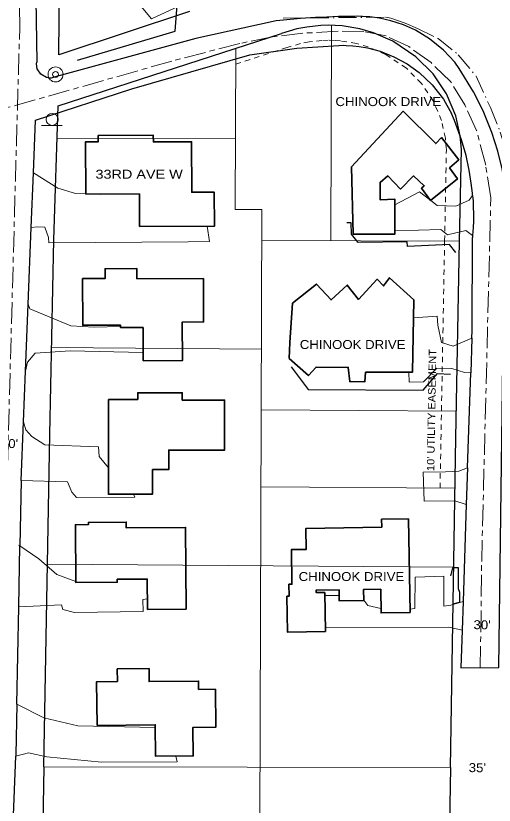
# Model space of a CAD drawing. Extents: x -861682 to -858969, y -1797841 to -1795153.
# Drawn here: x -860995 to -860675, y -1797216 to -1796688 of the extents above; entities that cross this region are included whole.
import ezdxf

# ---------------------------------------------------------------- set-up
doc = ezdxf.new("R2010")
doc.units = 0
doc.header["$LTSCALE"] = 2.4
for name, pattern in [('DOT_DASHED', [7.7, 5, -1.2, 0.3, -1.2]), ('LONG_DASH_SHORT_DASH', [9.9, 6, -1.2, 1.5, -1.2]), ('SHORT_DASHED', [2.7, 1.5, -1.2])]:
    doc.linetypes.add(name, pattern=pattern)
for name, color, linetype, lineweight in [('10', 7, 'Continuous', 25), ('11', 7, 'Continuous', 13), ('12', 7, 'Continuous', 35), ('14', 7, 'Continuous', 25), ('21', 7, 'Continuous', 13), ('30', 7, 'Continuous', 13), ('31', 7, 'Continuous', 13), ('32', 7, 'LONG_DASH_SHORT_DASH', 13), ('42', 7, 'Continuous', 25), ('46', 7, 'Continuous', 13), ('47', 7, 'SHORT_DASHED', 13), ('63', 7, 'DOT_DASHED', 13)]:
    doc.layers.add(name, color=color, linetype=linetype, lineweight=lineweight)
doc.layers.add('43', color=7, linetype='Continuous')

msp = doc.modelspace()

# ---------------------------------------------------------------- linework, layer by layer
at = {"layer": '10'}
for p, q in [((-860689.539, -1796835.154), (-860689.633, -1796836.516)), ((-860690.025, -1796903.667), (-860690.806, -1796926.828)), ((-860692.948, -1796990.368), (-860690.806, -1796926.828)), ((-860991.269, -1796998.783), (-860989.701, -1796959.723)), ((-860692.948, -1796990.368), (-860693.774, -1797014.844)), ((-860991.269, -1796998.783), (-860992.108, -1797042.6)), ((-860693.774, -1797014.844), (-860695.962, -1797079.745)), ((-860992.889, -1797083.299), (-860992.108, -1797042.6)), ((-860994.136, -1797148.307), (-860992.889, -1797083.299)), ((-860695.962, -1797079.745), (-860696.61, -1797098.951)), ((-860998.692, -1797277.689), (-860994.825, -1797183.063))]:
    msp.add_line(p, q, dxfattribs=at)
for points in [[(-860916.639, -1796531.103), (-860972.545, -1796545.521), (-860983.387, -1796550.997), (-860980.82, -1796719.365)], [(-860768.16, -1796688.758), (-860772.568, -1796688.802), (-860779.179, -1796688.94), (-860786.888, -1796689.21), (-860794.592, -1796689.598), (-860804.487, -1796690.269), (-860815.84, -1796691.279), (-860820.813, -1796691.804)], [(-860701.439, -1796719.429), (-860708.938, -1796711.364), (-860718.335, -1796703.724), (-860727.76, -1796698.028), (-860735.79, -1796694.4), (-860744.159, -1796691.642), (-860751.686, -1796689.967), (-860758.238, -1796689.091), (-860763.161, -1796688.778), (-860764.263, -1796688.748), (-860766.467, -1796688.731), (-860768.16, -1796688.758)], [(-860820.813, -1796691.804), (-860874.61, -1796703.591), (-860967.555, -1796728.994)], [(-860983.021, -1796793.297), (-860981.609, -1796758.099), (-860917.22, -1796737.296), (-860838.434, -1796714.546), (-860807.043, -1796709.934), (-860778.947, -1796708.168)], [(-860778.947, -1796708.168), (-860776.151, -1796708.12), (-860773.947, -1796708.151), (-860769.635, -1796708.386), (-860765.254, -1796708.864), (-860759.824, -1796709.798), (-860751.308, -1796712.058), (-860742.087, -1796715.695), (-860733.384, -1796720.438), (-860725.33, -1796726.215), (-860716.544, -1796734.55), (-860709.109, -1796744.11), (-860703.664, -1796753.68)], [(-860967.555, -1796728.994), (-860971.294, -1796729.991), (-860972.395, -1796729.978), (-860974.368, -1796729.618), (-860978.135, -1796727.412), (-860980.461, -1796723.717), (-860980.927, -1796720.462), (-860980.82, -1796719.365)], [(-860667.811, -1796801.476), (-860669.755, -1796790.631), (-860672.633, -1796778.858), (-860676.642, -1796766.259), (-860682.438, -1796751.966), (-860688.867, -1796739.167), (-860698.547, -1796723.507), (-860701.439, -1796719.429)], [(-860689.551, -1796808.418), (-860689.672, -1796806.801), (-860690.405, -1796800.231), (-860691.788, -1796791.525), (-860693.895, -1796781.835), (-860696.91, -1796771.237), (-860701.676, -1796758.268), (-860703.664, -1796753.68)], [(-860989.701, -1796959.723), (-860988.341, -1796925.855), (-860986.543, -1796881.068), (-860984.485, -1796829.787), (-860983.021, -1796793.297)], [(-860696.61, -1797098.951), (-860697.453, -1797123.953), (-860671.948, -1797123.851), (-860667.811, -1796801.476)], [(-860689.551, -1796808.418), (-860689.262, -1796812.296), (-860689.066, -1796816.699), (-860688.996, -1796820.005), (-860688.986, -1796822.209), (-860689.025, -1796825.514), (-860689.18, -1796829.919), (-860689.539, -1796835.154)], [(-860690.025, -1796903.667), (-860689.856, -1796898.626), (-860689.633, -1796836.516)], [(-860994.136, -1797148.307), (-860994.784, -1797182.056), (-860994.825, -1797183.063)]]:
    msp.add_lwpolyline(points, dxfattribs=at)
at = {"layer": '11'}
for p, q in [((-860992.984, -1797042.007), (-860992.108, -1797042.6)), ((-860778.687, -1797075.629), (-860788.31, -1797075.667))]:
    msp.add_line(p, q, dxfattribs=at)
for points in [[(-860917.95, -1796673.813), (-860904.185, -1796690.487), (-860886.27, -1796682.149), (-860889.617, -1796554.163), (-860889.673, -1796540.23), (-860887.335, -1796534.316), (-860882.579, -1796542.563), (-860882.222, -1796572.554), (-860882.597, -1796596.88), (-860881.856, -1796604.907), (-860856.836, -1796601.737), (-860864.668, -1796569.117)], [(-860948.073, -1796807.381), (-860954.962, -1796807.114), (-860966.784, -1796803.618), (-860983.021, -1796793.297)], [(-860935.223, -1796807.505), (-860938.428, -1796807.756), (-860943.977, -1796807.54)], [(-860741.477, -1796814.681), (-860724.945, -1796805.957), (-860717.552, -1796811.792), (-860713.336, -1796815.121), (-860700.818, -1796815.543), (-860691.86, -1796811.493), (-860689.551, -1796808.418)], [(-860867.012, -1796828.959), (-860865.327, -1796839.108), (-860879.732, -1796839.402), (-860972.778, -1796840.011), (-860973.028, -1796836.47), (-860975.417, -1796829.63), (-860980.378, -1796829.414), (-860984.485, -1796829.787)], [(-860741.581, -1796831.766), (-860725.786, -1796831.702), (-860710.674, -1796831.17), (-860706.409, -1796834.695), (-860694.14, -1796831.811), (-860689.539, -1796835.154)], [(-860924.846, -1796896.031), (-860942.559, -1796896.332), (-860958.149, -1796895.45), (-860985.353, -1796884.223), (-860986.543, -1796881.068)], [(-860729.091, -1796890.276), (-860713.275, -1796889.038), (-860712.778, -1796895.176), (-860710.37, -1796906.738), (-860702.567, -1796909.069), (-860690.025, -1796903.667)], [(-860909.659, -1796913.29), (-860958.554, -1796912.218), (-860981.928, -1796913.729), (-860987.099, -1796919.89), (-860988.341, -1796925.855)], [(-860732.213, -1796926.426), (-860731.99, -1796933.275), (-860722.309, -1796933), (-860713.372, -1796923.754), (-860703.452, -1796923.95), (-860694.939, -1796926.75), (-860690.806, -1796926.828)], [(-860932.904, -1796990.333), (-860939.141, -1796982.752), (-860939.639, -1796976.377), (-860975.305, -1796975.103), (-860984.066, -1796969.471), (-860988.098, -1796965), (-860989.701, -1796959.723)], [(-860692.948, -1796990.368), (-860698.689, -1796992.653), (-860707.661, -1796993.161), (-860722.539, -1796993.221), (-860721.989, -1797012.584), (-860701.443, -1797012.502), (-860693.774, -1797014.844)], [(-860916.064, -1797007.99), (-860915.179, -1797010.05), (-860954.146, -1797010.207), (-860957.466, -1797006.677), (-860960.327, -1796999.84), (-860991.269, -1796998.783)], [(-860954.695, -1797066.389), (-860967.4, -1797061.742), (-860979.486, -1797051.163), (-860992.108, -1797042.6)], [(-860731.405, -1797084.762), (-860728.077, -1797084.401), (-860727.925, -1797063.382), (-860708.798, -1797062.833), (-860708.717, -1797082.906), (-860703.997, -1797082.179), (-860695.962, -1797079.745)], [(-860906.817, -1797077.989), (-860909.946, -1797078.279), (-860909.678, -1797086.308), (-860955.491, -1797086.964), (-860963.291, -1797085.106), (-860964.248, -1797082.039), (-860992.889, -1797083.299)], [(-860750.778, -1797084.476), (-860759.494, -1797082.401), (-860762.258, -1797078.786)], [(-860787.983, -1797097.372), (-860705.355, -1797096.826), (-860696.61, -1797098.951)], [(-860901.56, -1797163.951), (-860953.296, -1797162.761), (-860975.989, -1797157.42), (-860994.136, -1797148.307)], [(-860887.936, -1797182.95), (-860887.074, -1797186.821), (-860937.612, -1797187.023), (-860973.996, -1797183.39), (-860986.287, -1797180.842), (-860994.825, -1797183.063)]]:
    msp.add_lwpolyline(points, dxfattribs=at)
at = {"layer": '12'}
for points in [[(-860769.465, -1796834.237), (-860770.59, -1796789.371), (-860736.023, -1796752.155), (-860714.209, -1796773.795), (-860710.447, -1796769.765), (-860698.815, -1796784.596), (-860704.934, -1796790.053), (-860699.709, -1796797.353), (-860717.599, -1796811.83), (-860723.772, -1796803.589), (-860721.89, -1796801.929), (-860729.001, -1796795.345), (-860737.704, -1796804.118), (-860746.241, -1796795.414), (-860751.419, -1796799.685), (-860751.373, -1796811.257), (-860741.455, -1796810.981), (-860741.597, -1796834.362)], [(-860948.111, -1796807.557), (-860912.214, -1796807.414), (-860912.127, -1796829.14), (-860862.062, -1796828.94), (-860862.153, -1796806.268), (-860877.267, -1796806.329), (-860877.403, -1796772.558), (-860902.907, -1796772.661), (-860902.925, -1796768.173), (-860939.766, -1796768.321), (-860939.749, -1796772.572), (-860948.25, -1796772.606)], [(-860950.245, -1796864.007), (-860950.12, -1796895.18), (-860924.851, -1796895.079), (-860924.844, -1796896.732), (-860909.73, -1796896.668), (-860909.636, -1796918.87), (-860883.427, -1796918.759), (-860883.536, -1796893.024), (-860869.361, -1796892.964), (-860869.484, -1796863.919), (-860913.875, -1796864.107), (-860913.904, -1796857.249), (-860935.157, -1796857.339), (-860935.129, -1796863.943)], [(-860728.904, -1796878.235), (-860729.655, -1796926.416), (-860761.065, -1796926.541), (-860761.511, -1796932.92), (-860771.667, -1796932.724), (-860772.65, -1796923.282), (-860794.141, -1796923.132), (-860799.314, -1796928.82), (-860812.113, -1796917.299), (-860811.683, -1796906.67), (-860809.898, -1796880.448), (-860793.891, -1796867.632), (-860784.166, -1796878.221), (-860773.342, -1796868.258), (-860765.746, -1796877.911), (-860753.284, -1796864.4), (-860749.015, -1796868.87), (-860745.022, -1796863.422)], [(-860932.917, -1796944.704), (-860932.899, -1797007.995), (-860903.38, -1797007.987), (-860903.384, -1796991.582), (-860892.581, -1796991.579), (-860892.585, -1796978.55), (-860855.32, -1796978.539), (-860855.33, -1796945.104), (-860883.556, -1796945.112), (-860883.557, -1796940.255), (-860913.33, -1796940.261), (-860913.329, -1796944.7)], [(-860880.871, -1797084.774), (-860881.326, -1797030.222), (-860920.999, -1797030.553), (-860921.032, -1797026.605), (-860946.284, -1797026.816), (-860946.271, -1797028.357), (-860955.016, -1797028.431), (-860954.689, -1797067.12), (-860926.995, -1797066.886), (-860927.012, -1797064.885), (-860906.93, -1797064.714), (-860906.757, -1797084.995)], [(-860732.33, -1797024.43), (-860731.371, -1797087.009), (-860750.735, -1797087.306), (-860750.978, -1797071.49), (-860762.368, -1797071.665), (-860762.254, -1797079.1), (-860778.63, -1797079.351), (-860778.745, -1797071.844), (-860794.012, -1797072.078), (-860793.986, -1797073.796), (-860788.34, -1797073.711), (-860787.948, -1797099.745), (-860813.264, -1797100.126), (-860813.624, -1797076.234), (-860812.182, -1797076.212), (-860812.304, -1797068.205), (-860810.325, -1797068.175), (-860810.675, -1797045.062), (-860800.737, -1797044.912), (-860800.949, -1797030.847), (-860750.27, -1797030.083), (-860750.351, -1797024.701)], [(-860940.544, -1797162.473), (-860901.579, -1797162.08), (-860901.367, -1797183.086), (-860876.236, -1797182.832), (-860876.428, -1797163.876), (-860861.187, -1797163.722), (-860861.444, -1797138.303), (-860872.625, -1797138.416), (-860872.681, -1797132.917), (-860905.705, -1797133.253), (-860905.794, -1797124.548), (-860926.992, -1797124.765), (-860926.906, -1797133.125), (-860940.843, -1797133.268)]]:
    msp.add_lwpolyline(points, close=True, dxfattribs=at)
at = {"layer": '14'}
for points in [[(-860953.666, -1796718.076), (-860888.328, -1796698.687), (-860884.96, -1796655.221), (-860884.454, -1796545.875)], [(-860700.852, -1796846.597), (-860704.889, -1796841.181), (-860732.987, -1796842.474), (-860733.235, -1796839.405), (-860766.06, -1796839.773), (-860770.569, -1796834.359), (-860770.599, -1796826.802), (-860773.67, -1796826.814)], [(-860810.91, -1796922.963), (-860799.513, -1796938.032), (-860722.523, -1796938.432), (-860713.121, -1796927.295), (-860704.381, -1796927.732)], [(-860702.548, -1797081.286), (-860698.304, -1797080.064), (-860698.101, -1797080.029), (-860698.127, -1797073.653), (-860699.081, -1797071.295), (-860698.902, -1797057.125), (-860702.916, -1797057.141), (-860704.311, -1797062.578)]]:
    msp.add_lwpolyline(points, dxfattribs=at)
at = {"layer": '21'}
msp.add_line((-860963.749, -1796761.615), (-860977.753, -1796761.669), dxfattribs=at)
msp.add_circle((-860970.511, -1796757.582), 4, dxfattribs=at)
at = {"layer": '30'}
for p, q in [((-860784.331, -1796838.686), (-860783.868, -1796694.796)), ((-860848.186, -1796817.747), (-860847.84, -1796710.147)), ((-860967.118, -1796770.206), (-860848.034, -1796770.59)), ((-860848.186, -1796817.747), (-860830.435, -1796817.804)), ((-860832.547, -1797473.823), (-860830.435, -1796817.804)), ((-860830.502, -1796838.537), (-860698.251, -1796838.963)), ((-860970.911, -1796909.957), (-860830.735, -1796911.028)), ((-860700.365, -1796952.629), (-860830.866, -1796951.63)), ((-860701.26, -1797004.063), (-860831.031, -1797003.07)), ((-860702.146, -1797056.876), (-860973.73, -1797054.797)), ((-860976.165, -1797190.148), (-860704.392, -1797190.659))]:
    msp.add_line(p, q, dxfattribs=at)
at = {"layer": '31'}
for radius in [5, 2]:
    msp.add_circle((-860968.27, -1796727.581), radius, dxfattribs=at)
at = {"layer": '32'}
for points in [[(-861016.908, -1797697.112), (-861016.908, -1797629.868), (-861015.071, -1797572.938), (-861015.071, -1797447.139), (-861012.317, -1797374.599), (-861007.726, -1797281.857), (-861003.087, -1797084.148), (-860992.207, -1796696.344), (-860992.984, -1796576.661), (-860989.487, -1796449.983), (-860987.933, -1796343.901), (-860987.544, -1796199.737), (-860984.047, -1796080.831), (-860987.933, -1795887.705), (-860991.735, -1795769.455)], [(-860684.409, -1797123.901), (-860683.488, -1797053.074), (-860677.405, -1796810.113), (-860680.788, -1796788.286), (-860686.861, -1796765.065), (-860694.72, -1796747.917), (-860704.366, -1796732.199), (-860717.227, -1796719.695), (-860732.231, -1796708.978), (-860747.235, -1796701.833), (-860762.239, -1796698.975), (-860779.387, -1796698.618), (-860802.965, -1796700.047), (-860823.328, -1796702.547), (-860845.12, -1796706.834), (-860890.49, -1796718.623), (-860993.655, -1796747.958)], [(-861336.345, -1797123.445), (-861333.081, -1796888.015), (-861331.83, -1796872.168), (-861327.659, -1796856.738), (-861321.821, -1796845.478), (-861312.646, -1796834.219), (-861305.557, -1796827.129), (-861293.463, -1796820.457), (-861279.702, -1796815.453), (-861249.874, -1796808.735), (-861088.25, -1796770.144), (-860993.655, -1796747.958)]]:
    msp.add_lwpolyline(points, dxfattribs=at)
at = {"layer": '42'}
for p, q in [((-860698.251, -1796838.963), (-860697.069, -1796777.651)), ((-860972.172, -1796968.212), (-860969.356, -1796838.089)), ((-860700.693, -1796970.289), (-860698.251, -1796838.963)), ((-860976.165, -1797190.148), (-860972.172, -1796968.212)), ((-860704.392, -1797190.659), (-860700.693, -1796970.289)), ((-860976.165, -1797190.148), (-860978.624, -1797331.669)), ((-860704.392, -1797190.659), (-860706.531, -1797334.294))]:
    msp.add_line(p, q, dxfattribs=at)
for points in [[(-860878.673, -1796685.416), (-860966.096, -1796714.466), (-860964.664, -1796570.952), (-860876.438, -1796558.754)], [(-860697.069, -1796777.651), (-860697.813, -1796768.569), (-860700.804, -1796755.237), (-860707.035, -1796740.525), (-860716.01, -1796727.197), (-860727.419, -1796715.708), (-860742.923, -1796705.325), (-860755.877, -1796699.732), (-860764.961, -1796697.131), (-860776.643, -1796695.203), (-860781.375, -1796694.853), (-860786.121, -1796694.744), (-860790.867, -1796694.879), (-860800.305, -1796695.878), (-860806.906, -1796697.171), (-860817.221, -1796700.242)], [(-860969.356, -1796838.089), (-860966.403, -1796748.502), (-860817.221, -1796700.242)]]:
    msp.add_lwpolyline(points, dxfattribs=at)
at = {"layer": '47'}
for p, q in [((-860847.874, -1796720.668), (-860814.262, -1796709.795)), ((-860708.249, -1796838.772), (-860707.077, -1796777.961)), ((-860711.321, -1797003.986), (-860708.249, -1796838.775))]:
    msp.add_line(p, q, dxfattribs=at)
msp.add_lwpolyline([(-860707.077, -1796777.961), (-860707.723, -1796770.079), (-860710.364, -1796758.306), (-860715.868, -1796745.312), (-860723.775, -1796733.57), (-860733.812, -1796723.462), (-860747.727, -1796714.143), (-860759.249, -1796709.168), (-860767.159, -1796706.904), (-860777.828, -1796705.143), (-860781.859, -1796704.845), (-860786.094, -1796704.747), (-860790.198, -1796704.864), (-860798.815, -1796705.776), (-860804.513, -1796706.892), (-860814.262, -1796709.795)], dxfattribs=at)
at = {"layer": '63'}
msp.add_lwpolyline([(-860816.097, -1796689.896), (-860747.848, -1796689.386), (-860744.303, -1796690.08), (-860734.607, -1796693.348), (-860726.327, -1796696.857), (-860712.603, -1796703.651), (-860699.098, -1796714.46), (-860687.232, -1796728.819), (-860677.703, -1796749.563), (-860671.024, -1796766.067), (-860663.127, -1796792.014)], dxfattribs=at)

# ---------------------------------------------------------------- texts
at = {"layer": '43', "width": 1.1}
for s, rotation, p in [("60'", 358.37, (-861004.852, -1796976.953)), ("30'", 359.21, (-860689.004, -1797098.194)), ("35'", 359.102, (-860692.201, -1797193.659))]:
    msp.add_text(s, height=6, rotation=rotation, dxfattribs=at).set_placement(p)
at = {"layer": '46'}
for s, width, p in [('CHINOOK DRIVE', 1.1, (-860781.222, -1796748.726)), ('33RD AVE W', 1.2, (-860941.554, -1796797.211)), ('CHINOOK DRIVE', 1.1, (-860805.036, -1796911.01)), ('CHINOOK DRIVE', 1.1, (-860805.804, -1797066.032))]:
    msp.add_text(s, height=6, dxfattribs=dict(at, width=width)).set_placement(p)
at = {"layer": '47', "width": 1.1}
msp.add_text("10' UTILITY EASEMENT", height=5, rotation=89.037, dxfattribs=at).set_placement((-860715.175, -1796992.551))

doc.saveas('drawing.dxf')
